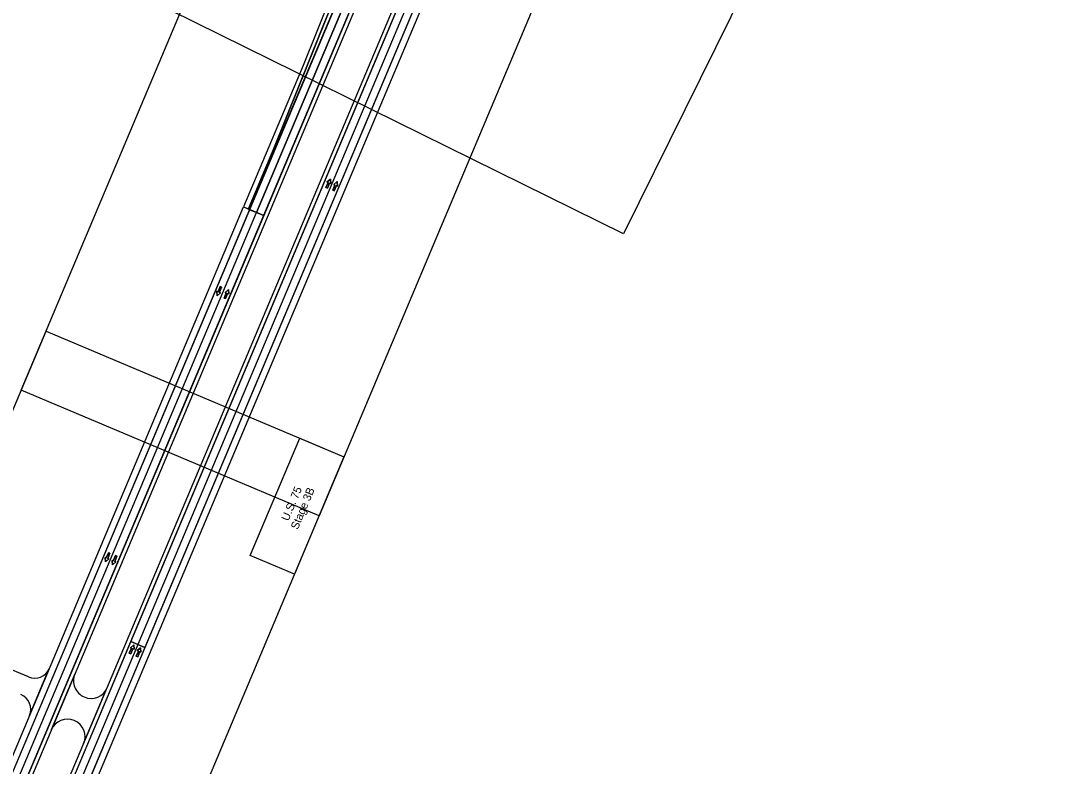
# Model space of a CAD drawing. Extents: x 14104283 to 14121738, y 8635219 to 8671666.
# Drawn here: x 14118056 to 14119692, y 8666575 to 8667739 of the extents above; entities that cross this region are included whole.
import ezdxf

# ---------------------------------------------------------------- set-up
doc = ezdxf.new("R2010")
doc.units = 0
for name, color, linetype in [('Cell', 7, 'Continuous'), ('Default', 7, 'Continuous'), ('dsnNonPlotable', 7, 'Continuous'), ('dsnPaintExistingBrokenLaneLineWhite', 7, 'Continuous'), ('dsnPaintExistingEdgeLineLeftYellow', 7, 'Continuous'), ('dsnPaintExistingEdgeLineRightWhite', 7, 'Continuous'), ('dsnShadingPaved', 7, 'Continuous'), ('dsnStgShadingPrevPav', 7, 'Continuous'), ('dsnTextOverlapEven', 7, 'Continuous')]:
    doc.layers.add(name, color=color, linetype=linetype)

msp = doc.modelspace()

# ---------------------------------------------------------------- linework, layer by layer
at = {"layer": 'Cell'}
for points in [[(14118535, 8667477.3), (14118532.6, 8667478.3), (14118536, 8667486.4), (14118534.2, 8667487.1), (14118539.5, 8667491.7), (14118540, 8667484.7), (14118538.3, 8667485.4)], [(14118545.6, 8667473.4), (14118543.3, 8667474.4), (14118546.6, 8667482.4), (14118544.9, 8667483.2), (14118550.1, 8667487.8), (14118550.6, 8667480.8), (14118548.9, 8667481.5)], [(14118367.3, 8667323.8), (14118369.6, 8667322.9), (14118366.3, 8667314.8), (14118368, 8667314.1), (14118362.8, 8667309.5), (14118362.2, 8667316.5), (14118364, 8667315.7)], [(14118375.7, 8667305), (14118373.4, 8667305.9), (14118376.7, 8667314), (14118375, 8667314.7), (14118380.3, 8667319.3), (14118380.8, 8667312.3), (14118379, 8667313.1)], [(14118192.7, 8666908), (14118195, 8666907.1), (14118191.7, 8666899), (14118193.4, 8666898.3), (14118188.1, 8666893.7), (14118187.6, 8666900.6), (14118189.3, 8666899.9)], [(14118203.7, 8666903.4), (14118206, 8666902.4), (14118202.7, 8666894.3), (14118204.5, 8666893.6), (14118199.2, 8666889), (14118198.7, 8666896), (14118200.4, 8666895.3)], [(14118227.7, 8666749.8), (14118225.4, 8666750.8), (14118228.7, 8666758.9), (14118227, 8666759.6), (14118232.3, 8666764.2), (14118232.8, 8666757.2), (14118231, 8666757.9)], [(14118238.5, 8666745.3), (14118236.2, 8666746.2), (14118239.5, 8666754.3), (14118237.8, 8666755), (14118243, 8666759.6), (14118243.5, 8666752.7), (14118241.8, 8666753.4)]]:
    msp.add_lwpolyline(points, close=True, dxfattribs=at)
for points in [[(14118538.3, 8667485.4), (14118540, 8667484.7), (14118539.5, 8667491.7), (14118534.2, 8667487.1), (14118536, 8667486.4), (14118532.6, 8667478.3), (14118535, 8667477.3), (14118538.3, 8667485.4)], [(14118548.9, 8667481.5), (14118550.6, 8667480.8), (14118550.1, 8667487.8), (14118544.9, 8667483.2), (14118546.6, 8667482.4), (14118543.3, 8667474.4), (14118545.6, 8667473.4), (14118548.9, 8667481.5)], [(14118364, 8667315.7), (14118362.2, 8667316.5), (14118362.8, 8667309.5), (14118368, 8667314.1), (14118366.3, 8667314.8), (14118369.6, 8667322.9), (14118367.3, 8667323.8), (14118364, 8667315.7)], [(14118379, 8667313.1), (14118380.8, 8667312.3), (14118380.3, 8667319.3), (14118375, 8667314.7), (14118376.7, 8667314), (14118373.4, 8667305.9), (14118375.7, 8667305), (14118379, 8667313.1)], [(14118189.3, 8666899.9), (14118187.6, 8666900.6), (14118188.1, 8666893.7), (14118193.4, 8666898.3), (14118191.7, 8666899), (14118195, 8666907.1), (14118192.7, 8666908), (14118189.3, 8666899.9)], [(14118200.4, 8666895.3), (14118198.7, 8666896), (14118199.2, 8666889), (14118204.5, 8666893.6), (14118202.7, 8666894.3), (14118206, 8666902.4), (14118203.7, 8666903.4), (14118200.4, 8666895.3)], [(14118231, 8666757.9), (14118232.8, 8666757.2), (14118232.3, 8666764.2), (14118227, 8666759.6), (14118228.7, 8666758.9), (14118225.4, 8666750.8), (14118227.7, 8666749.8), (14118231, 8666757.9)], [(14118241.8, 8666753.4), (14118243.5, 8666752.7), (14118243, 8666759.6), (14118237.8, 8666755), (14118239.5, 8666754.3), (14118236.2, 8666746.2), (14118238.5, 8666745.3), (14118241.8, 8666753.4)]]:
    msp.add_lwpolyline(points, dxfattribs=at)
at = {"layer": 'Default'}
for p, q in [((14118528.4, 8667730.9), (14118643.5, 8668017.6)), ((14118576.7, 8667832.4), (14118534.2, 8667731.7)), ((14118534.2, 8667731.7), (14118412.9, 8667443.5)), ((14118412.9, 8667443.5), (14118528.4, 8667730.9)), ((14118435.4, 8667434.9), (14118413.2, 8667444.3))]:
    msp.add_line(p, q, dxfattribs=at)
for points in [[(14118653, 8668013.6), (14118412.9, 8667444.4), (14118424.3, 8667439.6), (14118664.1, 8668009)], [(14118435.4, 8667434.9), (14118675.1, 8668004.3), (14118664.1, 8668009), (14118424.2, 8667439.7)]]:
    msp.add_lwpolyline(points, close=True, dxfattribs=at)
for points in [[(14118413.2, 8667444.3), (14110818.4, 8649409.2), (14109142.6, 8645431.4)], [(14109164.7, 8645422.1), (14110840.5, 8649399.8), (14118435.4, 8667434.9)]]:
    msp.add_lwpolyline(points, dxfattribs=at)
at = {"layer": 'dsnNonPlotable'}
for points in [[(14118092, 8667853.7), (14118786.8, 8669258.8), (14119692.1, 8668811.2), (14118997.4, 8667406.1)], [(14118056.5, 8667161.9), (14118665.1, 8668606.4), (14119130.4, 8668410.4), (14118521.9, 8666965.8)], [(14117486.7, 8665809.5), (14118095.3, 8667254.1), (14118560.7, 8667058), (14117952.1, 8665613.5)]]:
    msp.add_lwpolyline(points, close=True, dxfattribs=at)
at = {"layer": 'dsnPaintExistingBrokenLaneLineWhite'}
for p, q in [((14114932.5, 8658913.4), (14118863.7, 8668248.6)), ((14118664.1, 8668009), (14118424.3, 8667439.6)), ((14110829.5, 8649404.5), (14118424.3, 8667439.6))]:
    msp.add_line(p, q, dxfattribs=at)
at = {"layer": 'dsnPaintExistingEdgeLineLeftYellow'}
for p, q in [((14115900.9, 8661244), (14118817.4, 8668169.6)), ((14118675.1, 8668004.3), (14118435.4, 8667434.9)), ((14118435.4, 8667434.9), (14115816.1, 8661215.2))]:
    msp.add_line(p, q, dxfattribs=at)
at = {"layer": 'dsnPaintExistingEdgeLineRightWhite'}
for p, q in [((14110924.4, 8649364.5), (14118874.7, 8668243.7)), ((14118643.5, 8668017.6), (14118412.9, 8667444.4)), ((14118413.2, 8667444.3), (14115798.8, 8661235.7))]:
    msp.add_line(p, q, dxfattribs=at)
at = {"layer": 'dsnShadingPaved'}
for p, q in [((14115901.2, 8661244.5), (14118227.7, 8666769.2)), ((14118227.7, 8666769.2), (14118249.8, 8666759.9)), ((14118249.8, 8666759.9), (14115923.3, 8661235.2))]:
    msp.add_line(p, q, dxfattribs=at)
msp.add_lwpolyline([(14118227.7, 8666769.2), (14118817.4, 8668169.6), (14118839.4, 8668160), (14118249.8, 8666759.9)], close=True, dxfattribs=at)
at = {"layer": 'dsnStgShadingPrevPav'}
for p, q in [((14115895.6, 8661246.8), (14118811.5, 8668171)), ((14118848.4, 8668155.5), (14115932.5, 8661231.3)), ((14118653, 8668013.6), (14115794, 8661224.5)), ((14118652.6, 8668013.1), (14118415.9, 8667450.9)), ((14118458, 8667555.6), (14118643.5, 8668017.6)), ((14118458, 8667555.6), (14118643.5, 8668017.6)), ((14118638, 8668019.9), (14118497.2, 8667669.3)), ((14115816.1, 8661215.2), (14118675.1, 8668004.3)), ((14115816.1, 8661215.2), (14118675.1, 8668004.3)), ((14118680.7, 8668002), (14115821.7, 8661212.9)), ((14118497.2, 8667669.3), (14118404, 8667448.1)), ((14118411.4, 8667445), (14118458, 8667555.6)), ((14118411.4, 8667445), (14118458, 8667555.6)), ((14118415.9, 8667450.9), (14118413.1, 8667444.3)), ((14110809.2, 8649413), (14118404, 8667448.1)), ((14118413.2, 8667444.3), (14110818.4, 8649409.2)), ((14118404, 8667448.1), (14118411.4, 8667445)), ((14118404, 8667448.1), (14118413.2, 8667444.3)), ((14118413.2, 8667444.3), (14118411.4, 8667445)), ((14118067.7, 8666713.9), (14118027.9, 8666730.6)), ((14118069.4, 8666653.5), (14118100.4, 8666727.2)), ((14118140.2, 8666718.6), (14118103.3, 8666631)), ((14118154, 8666609.7), (14118190.9, 8666697.3))]:
    msp.add_line(p, q, dxfattribs=at)
for centre, radius, start, end in [((14118077.4, 8666736.9), 25, 247.1633, 337.1633), ((14118165.6, 8666707.9), 27.5, 157.1633, 247.1633), ((14118046.4, 8666663.2), 25, 337.1633, 67.1633), ((14118165.6, 8666707.9), 27.5, 247.1633, 337.1633), ((14118128.7, 8666620.4), 27.5, 67.1633, 157.1633), ((14118128.7, 8666620.4), 27.5, 337.1633, 67.1633)]:
    msp.add_arc(centre, radius, start, end, dxfattribs=at)
at = {"layer": 'dsnTextOverlapEven'}
for points in [[(14118560.7, 8667058), (14118483.3, 8666874.4), (14118414.2, 8666903.5), (14118491.6, 8667087.1)], [(14118414.2, 8666903.5), (14118491.6, 8667087.1), (14118560.7, 8667058), (14118483.3, 8666874.4)]]:
    msp.add_lwpolyline(points, close=True, dxfattribs=at)

# ---------------------------------------------------------------- texts
for s, p in [('U.S. 75', (14118473.9, 8666956.5)), ('Stage 3B', (14118488.6, 8666943.2))]:
    msp.add_text(s, height=12.5, rotation=67.1547, dxfattribs=at).set_placement(p)

doc.saveas('drawing.dxf')
